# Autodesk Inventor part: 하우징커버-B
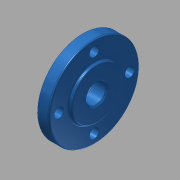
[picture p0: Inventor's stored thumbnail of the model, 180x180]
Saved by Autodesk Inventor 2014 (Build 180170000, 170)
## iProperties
Created: 2018-01
Part Number: 하우징커버-B
Material: 알루미늄 6061
Document SubType Name: Modeling
Designer: mduedu
Density: 2.71 g/cm^3
Appearance: 청록색
Mass: 8.4704 g
Surface Area: 21.4635 cm^2
Volume: 3.12561 cm^3
Author: mduedu
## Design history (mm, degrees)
sketch "스케치1"
  geometry: C1 r 16 at (0, 0); 1 further point
  constraints: 1 centre point, 1 coincident
  dimensions: "d0" = 32 diameter of C1
extrude "돌출1" new body sketch "스케치1" distance "d1" = 4; taper "d2" = 0 deg
sketch "스케치2"
  geometry: C1 r 9 at (0, 0); 1 further point
  constraints: 1 centre point, 1 coincident
  dimensions: "d3" = 18 diameter of C1
extrude "돌출2" join sketch "스케치2" distance "d4" = 1; taper "d5" = 0 deg
fillet "모깎기1" dims "d6" = 0.5
fillet "모깎기2" dims "d7" = 0.5
hole "구멍1" diameter "d10" = 7; stored, may be unused: countersink angle "d14" = 90 deg, drill point angle "d16" = 118 deg; dims "d8" = 10, "d9" = 10, "d11" = 6, "d12" = 4, "d13" = 2, "d15" = 8
chamfer "모따기1" distance "d17" = 0.5; stored, may be unused: second distance "d18" = 2, angle "d19" = 45 deg
sketch "스케치3" dims "d21" = 25
  geometry: 6 further points
  constraints: 2 vertical alignment, 1 coincident, 7 other
  dimensions: "d24" = 360 deg dimension on point (0, 0) point (0, 12.5) (derived)
sketch "스케치4"
  geometry: 4 further points
  constraints: 4 other
hole "구멍2" sketch "스케치4" at (-12.5, 0), (0, -12.5), (12.5, 0), (0, 12.5) diameter "d26" = 3.4; stored, may be unused: countersink angle "d30" = 90 deg, drill point angle "d32" = 0 deg; dims "d27" = 6, "d28" = 4, "d29" = 2, "d31" = 8
node "솔리드1"
